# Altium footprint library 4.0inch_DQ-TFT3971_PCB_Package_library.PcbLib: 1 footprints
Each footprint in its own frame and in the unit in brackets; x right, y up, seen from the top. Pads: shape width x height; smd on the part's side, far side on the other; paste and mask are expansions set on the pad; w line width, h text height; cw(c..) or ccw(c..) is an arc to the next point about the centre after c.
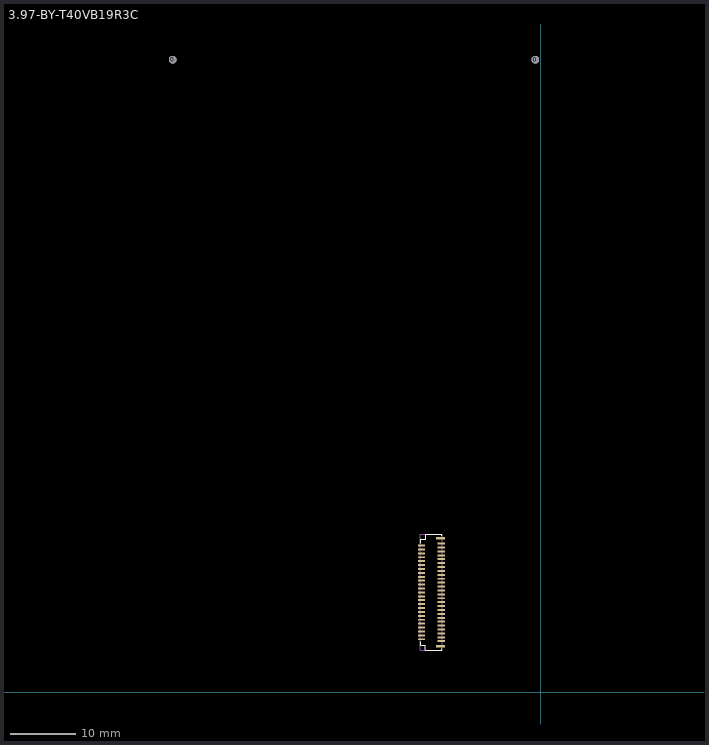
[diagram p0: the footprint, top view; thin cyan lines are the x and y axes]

## 3.97-BY-T40VB19R3C [mm]
pads (55):
  round 1.2 hole 1.2 unplated: 0(-56.54,97.2) 0(-0.8,97.2)
  rect 1.15x0.3 smd: 1(-15.296,22.834) 3(-15.296,22.234) 5(-15.296,21.634) 7(-15.296,21.034) 9(-15.296,20.434) 11(-15.296,19.834) 13(-15.296,19.234) 15(-15.296,18.634) 17(-15.296,18.034) 19(-15.296,17.434) 21(-15.296,16.834) 23(-15.296,16.234) 25(-15.296,15.634) 27(-15.296,15.034) 29(-15.296,14.434) 31(-15.296,13.834) 33(-15.296,13.234) 35(-15.296,12.634) 37(-15.296,12.034) 39(-15.296,11.434) 41(-15.296,10.834) 43(-15.296,10.234) 45(-15.296,9.634) 47(-15.296,9.034) 49(-15.296,8.434) 51(-15.296,7.834)
  rect 1x0.3 smd: 2(-18.296,22.534) 4(-18.296,21.934) 6(-18.296,21.334) 8(-18.296,20.734) 10(-18.296,20.134) 12(-18.296,19.534) 14(-18.296,18.934) 16(-18.296,18.334) 18(-18.296,17.734) 20(-18.296,17.134) 22(-18.296,16.534) 24(-18.296,15.934) 26(-18.296,15.334) 28(-18.296,14.734) 30(-18.296,14.134) 32(-18.296,13.534) 34(-18.296,12.934) 36(-18.296,12.334) 38(-18.296,11.734) 40(-18.296,11.134) 42(-18.296,10.534) 44(-18.296,9.934) 46(-18.296,9.334) 48(-18.296,8.734) 50(-18.296,8.134)
  rect 1.35x0.4 smd: 60(-15.396,7.034) 61(-15.396,23.634)
Top Overlay:
  lines w0.152: -18.448,7.755 -18.448,7.196 -17.686,7.196 -17.686,6.434 -15.172,6.434 ; -18.423,22.915 -18.423,23.474 -17.661,23.474 -17.661,24.236 -15.146,24.236 ; -15.172,6.51 -15.172,6.637 ; -15.146,24.033 -15.146,24.16
Bottom Overlay:
  lines w0.152: -57.34,0 0,0 0,97.8 -57.34,97.8 -57.34,0
Mechanical 13:
  lines w0.1: -18.499,6.408 -18.499,24.236 -15.07,24.236 -15.07,6.408 -18.499,6.408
